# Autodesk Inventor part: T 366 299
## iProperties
Company: Mayer & Müller AG Schaltgeräte
Created: 2006-03
Part Number: T 366 299
Material: 1.0309
Document SubType Name: Modeling
Designer: I.Baliuc
Description: Buchse
Density: 7.84 g/cm^3
HalbzeugNorm: DIN 2391
Zweck: Schaltrohr Trenner
Abmessung: Präz. Rohr 32 x 4
Author: T.Messerschmitt
Keywords: 381135
Revision Number: 366299
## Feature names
1. Drehung1 [Revolution]
